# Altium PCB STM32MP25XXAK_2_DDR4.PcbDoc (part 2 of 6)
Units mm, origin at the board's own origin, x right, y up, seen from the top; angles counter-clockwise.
Board outline 120 x 79.6 mm, 4 copper layers (Top Layer, Signal Layer 1, Signal Layer 2, Bottom Layer), stack 1.614 mm thick; 243 components, 152 nets, 1304 pads, 784 vias.
Unrouted connection lines stored in the file: 6.
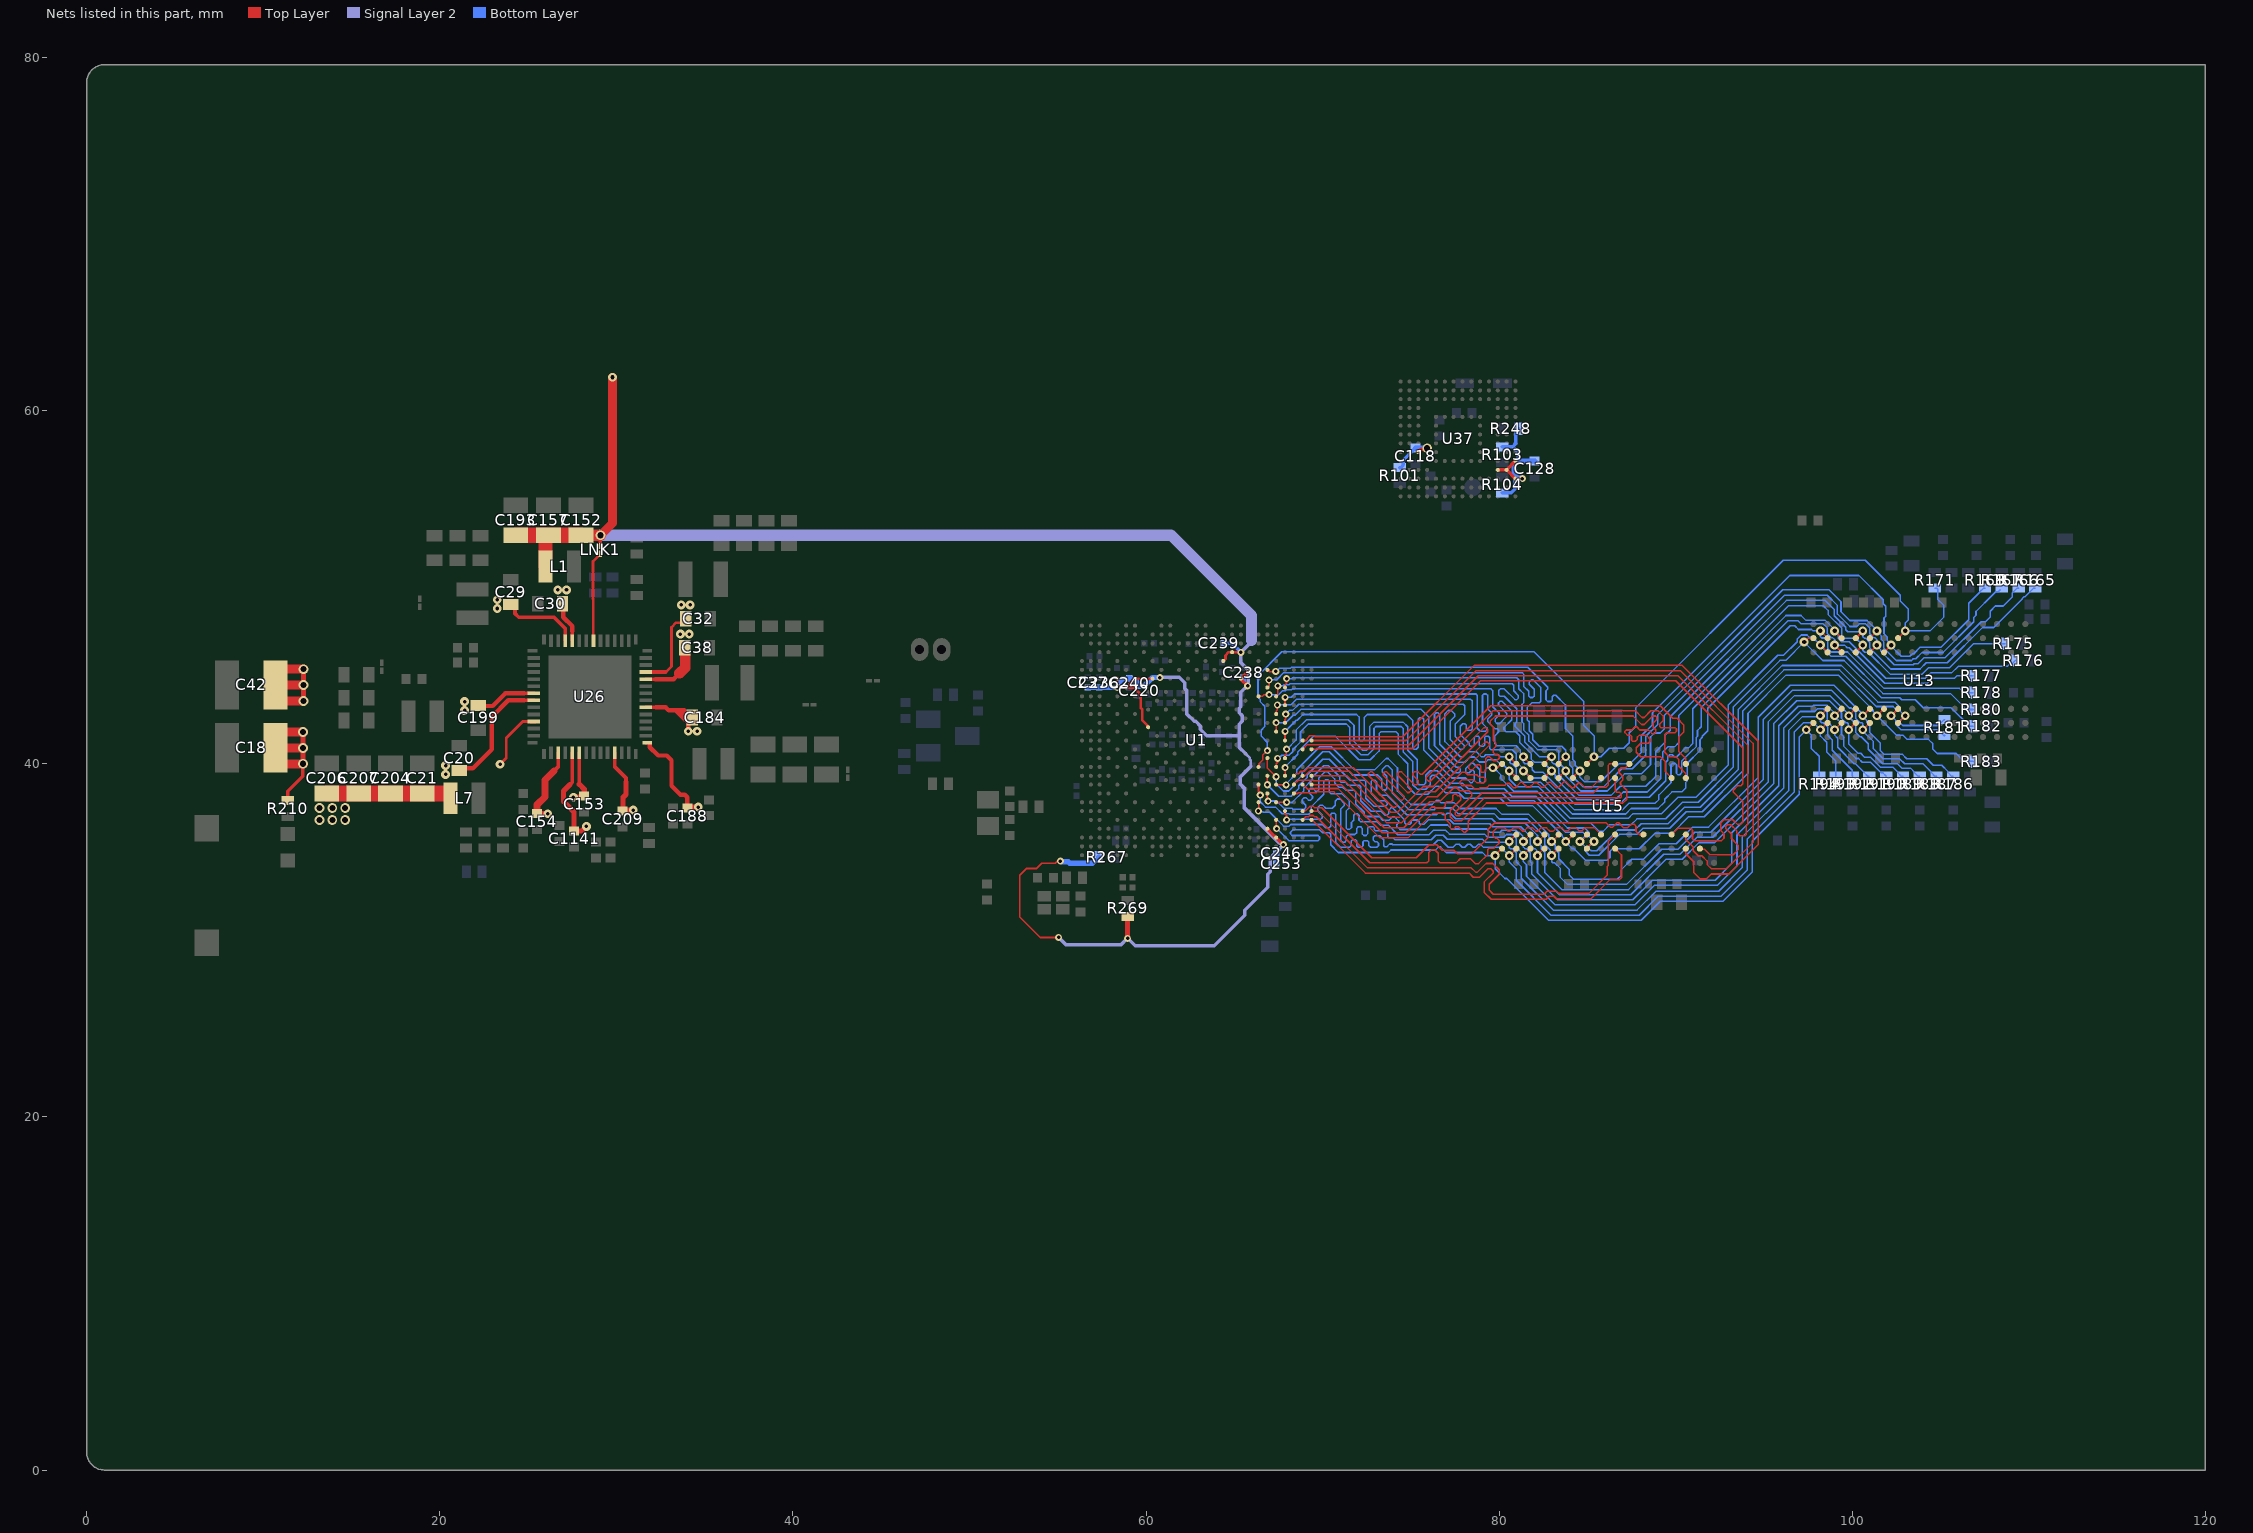
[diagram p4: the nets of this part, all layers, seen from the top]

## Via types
v1: diameter 0.55, hole 0.35, Top Layer to Bottom Layer, 256 vias
v2: diameter 0.4, hole 0.2, Top Layer to Bottom Layer, tented both sides, 235 vias
v3: diameter 0.5, hole 0.2, Top Layer to Bottom Layer, 146 vias
v4: diameter 0.5, hole 0.25, Top Layer to Bottom Layer, 143 vias
v5: diameter 0.5, hole 0.25, Top Layer to Bottom Layer, tented both sides, 4 vias

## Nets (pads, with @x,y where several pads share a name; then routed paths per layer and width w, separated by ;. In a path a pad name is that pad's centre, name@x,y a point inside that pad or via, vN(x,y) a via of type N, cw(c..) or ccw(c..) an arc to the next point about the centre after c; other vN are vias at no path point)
1V8: C118.2 C128.2 C152.2 C157.2 C193.2 C220.2 C236.2 C237.2 C238.2 C239.2 C240.2 C246.2 C253.2 L1.2 LNK1.2 R101.2 R103.2 R104.2 R248.2 R267.2 R269.1 U1.1E1 U1.AD22 U1.AE23 U1.D18 U1.E17 U1.F20 U1.G5 U1.G7 U1.G9 U1.G19 U1.H6 U37.C6 U37.M4 U37.N4 U37.P3 U37.P5 | length 134.2
  Top Layer w0.1: v2(55.049,30.165) 54.012,30.165 52.854,31.323 52.854,33.688 53.244,34.078 53.813,34.078 54.103,34.368 54.86,34.368 54.967,34.474 55.127,34.474 v2(55.146,34.494)
  Top Layer w0.15: U1.G5@58.375,44.825 v2(58.375,44.325) U1.H6@58.875,44.325 ; U1.1E1@60.125,42.075 60.125,42.097 60.085,42.137 60.085,42.17 59.791,42.464 59.791,43.079 59.702,43.168 59.702,43.926 59.304,44.325 U1.H6@58.875,44.325 ; U1.G9@60.375,44.825 U1.G7@59.375,44.825 U1.H6@58.875,44.325 ; U1.E17@64.375,45.825 64.375,45.828 64.5,45.953 64.5,46.139 64.683,46.322 U1.D18@64.872,46.322 ; U1.D18@64.875,46.325 65.372,46.325 v2(65.378,46.319) ; U37.P3@80.925,56.155 v2(81.325,56.155)
  Top Layer w0.18: v2(65.755,44.415) 65.4,44.77 65.4,44.786 65.375,44.811 U1.G19@65.375,44.825 U1.F20@65.875,45.325 ; U1.AD22@66.875,36.325 66.875,36.32 67.002,36.193 67.002,36.169 67.236,35.935 67.257,35.935 67.367,35.825 U1.AE23@67.375,35.825 v2(67.78,35.42)
  Top Layer w0.2: LNK1.2@29.1,52.348 v1(29.1,52.95) ; U37.C6@75.425,57.655 75.602,57.832 75.877,57.832 v1(75.925,57.88) ; U37.M4@79.925,56.655 U37.N4@80.425,56.655 ; U37.P3@80.925,56.155 U37.N4@80.425,56.655 ; U37.P5@80.925,57.155 U37.N4@80.425,56.655
  Top Layer w0.3: R269.1@58.956,31.358 58.956,30.117 v2(58.962,30.112)
  Top Layer w0.5: v1(29.1,52.95) 29.78,53.63 v4(29.78,61.9)
  Top Layer w0.64: C152.2@28,52.95 v1(29.1,52.95)
  Top Layer w0.8: L1.2@25.995,51.175 25.995,52.9 26.045,52.95 C157.2@26.15,52.95
  Top Layer w0.9: C193.2@24.3,52.95 C157.2@26.045,52.95 ; C157.2@26.15,52.95 C152.2@28,52.95
  Signal Layer 2 w0.15: 65.64,40.572 65.885,40.327 65.885,40.243 65.93,40.198 65.93,39.851
  Signal Layer 2 w0.2: v2(55.049,30.165) 55.449,29.766 58.598,29.766 v2@58.944,30.112 ; v2(58.962,30.112) 59.386,29.688 63.861,29.688 65.603,31.43 65.603,31.711 66.9,33.008 66.9,33.754 67.041,33.895 67.041,34.681 v2(67.78,35.42) 67.726,35.42 67.633,35.513 67.566,35.513 65.552,37.527 65.552,38.632 65.349,38.835 65.349,39.271 65.93,39.851 ; v2(60.79,44.885) 60.811,44.906 61.89,44.906 62.2,44.596 62.2,44.264 62.32,44.144 62.32,42.814 62.725,42.409 62.81,42.409 63.077,42.143 63.077,41.961 63.445,41.593 65.285,41.593 65.285,42.251 65.44,42.406 65.44,42.738 65.284,42.894 65.284,43.14 65.375,43.231 65.375,44.053 v2@65.734,44.411 ; 65.285,41.575 65.285,40.928 65.64,40.572 ; 65.794,44.612 65.794,45.317 65.378,45.733 v2(65.378,46.319) 65.933,46.874 65.933,46.95
  Signal Layer 2 w0.64: v1(29.1,52.95) 61.405,52.95 ; 61.411,52.956 65.971,48.396 65.971,46.988
  Bottom Layer w0.18: C238.2@65.5,44.883 65.585,44.798 65.585,44.63 65.755,44.46 v2(65.755,44.415) ; C246.2@67.391,34.986 67.436,34.986 67.46,35.01 67.46,35.054 67.57,35.164 67.57,35.175 67.78,35.385 v2(67.78,35.42)
  Bottom Layer w0.2: C239.2@64.4,46.837 64.86,46.837 v2(65.378,46.319) ; R101.2@74.375,56.775 74.425,56.775 74.58,56.93 74.58,57.2 75.08,57.7 75.08,57.725 75.235,57.88 C118.2@75.26,57.88 ; R103.2@80.171,57.961 80.769,57.961 ; R104.2@80.175,55.355 80.69,55.355 80.885,55.55 80.885,55.998 81.061,56.174 ; 81.075,57.136 81.075,57.655 80.769,57.961 ; R248.2@81.107,58.98 80.952,58.825 80.952,58.144 80.769,57.961
  Bottom Layer w0.25: C253.2@67.391,34.385 C246.2@67.391,34.925
  Bottom Layer w0.3: v2(55.146,34.494) 55.165,34.474 55.236,34.474 55.259,34.452 55.612,34.452 55.689,34.375 56.975,34.375 57.123,34.523 57.218,34.523 57.323,34.628 R267.2@57.323,34.723 ; C237.2@56.696,44.325 C236.2@57.35,44.325 v2(58.375,44.325) ; v2@58.386,44.325 v2(58.375,44.325) ; C240.2@58.984,44.85 C240.2@59.05,44.85 59.125,44.85 59.15,44.825 59.19,44.825 59.3,44.715 59.399,44.715 59.54,44.574 59.54,44.475 C220.2@59.609,44.406 59.634,44.431 59.911,44.431 60.372,44.892 60.783,44.892 v2(60.79,44.885) ; C240.2@59.025,44.825 58.689,44.825 58.394,44.53 58.394,44.344 v2(58.375,44.325) ; C118.2@75.26,57.88 v1(75.925,57.88) ; v2(81.325,56.155) 81.306,56.174 81.061,56.174 80.867,56.368 80.867,56.928 81.075,57.136 81.306,57.136 81.325,57.155 C128.2@82.015,57.155
1V8_FB: LNK1.1 U26.35 | length 5.1
  Top Layer w0.15: U26.35@28.7,46.97 28.7,49.311 28.675,49.336 28.675,51.473 LNK1.1@29.1,51.898
3V3: C21.2 C154.2 C204.2 C206.2 C207.2 L7.2 U26.3 U26.53 | length 15.3
  Top Layer w0.15: v3(23.41,39.977) 23.762,40.329 23.762,41.465 24.697,42.4 U26.53@25.33,42.4 ; U26.53@25.12,42.369 25.419,42.369 U26.53@25.45,42.4
  Top Layer w0.21: 26.473,39.598 26.7,39.825 U26.3@26.7,40.63
  Top Layer w0.3: C154.2@25.475,37.175 C154.2@25.5,37.175 v3@26.085,37.175
  Top Layer w0.4: C154.2@25.5,37.175 25.514,37.189 25.514,37.685 25.96,38.131 25.96,39.085 26.473,39.598
  Top Layer w0.9: C206.2@13.587,38.323 C21.2@19,38.323 20.362,38.323 L7.2@20.387,38.298
  other v1: 13.187,36.823 13.912,36.823 14.637,36.823 13.187,37.498 13.912,37.498 14.637,37.498
  other v3: 26.11,37.175
5V_STLK: C18.1 C20.2 C29.2 C30.2 C32.2 C38.2 C42.1 C153.2 C184.2 C188.2 C199.2 C209.2 R210.1 U26.6 U26.11 U26.15 U26.20 U26.24 U26.25 U26.38 U26.39 U26.49 U26.50 | length 58.9
  Top Layer w0.15: 32.8,45.2 33.125,45.525 33.125,47.731 33.388,47.994 33.819,47.994 C32.2@33.925,48.1
  Top Layer w0.2: R210.1@11.386,37.915 11.386,38.449 12.244,39.307 v1@12.244,39.994
  Top Layer w0.21: C29.2@24.025,49.05 24.262,48.813 24.262,48.513 24.475,48.3 26.464,48.3 27.1,47.664 U26.39@27.1,46.97 ; 24.775,43.6 U26.50@25.33,43.6 ; 24.775,44 U26.49@25.33,44 ; U26.38@27.5,46.97 27.5,47.525 ; 27.9,38.85 U26.6@27.9,40.63 ; U26.11@29.9,40.63 29.9,39.843 30.54,39.203 30.54,38.975 ; U26.15@31.67,41.2 U26.15@31.745,41.2 U26.15@31.785,41.2 ; U26.20@31.67,43.2 32.225,43.2 ; U26.24@31.67,44.8 32.207,44.8 ; U26.25@31.67,45.2 32.8,45.2
  Top Layer w0.25: C20.2@21.1,39.75 21.875,39.75 22.95,40.825 22.95,42.669 23.881,43.6 24.775,43.6 ; C199.2@22.175,43.275 22.991,43.275 23.716,44 24.775,44 ; C30.2@26.925,49.075 26.994,49.006 26.994,48.308 27.5,47.802 27.5,47.525 ; 31.895,41.095 31.895,40.947 32.371,40.472 32.853,40.472 33.125,40.2 33.125,38.759 33.634,38.25 33.879,38.25 34.025,38.104 C188.2@34.025,37.55 ; 32.207,44.8 33.25,44.8 33.575,45.125 ; 32.225,43.2 32.788,43.2 32.963,43.025 33.358,43.025 ; v3(34.075,41.85) 34.075,42.308 33.358,43.025 ; 33.358,43.025 33.579,43.025 ; 33.579,43.025 33.847,43.025 33.972,42.9 34.05,42.9 34.247,42.703 34.247,42.625 34.246,42.627 33.977,42.627 33.579,43.025
  Top Layer w0.3: v1@12.25,40 12.25,40.906 v1@12.25,41.8 ; v1@12.275,43.563 v1@12.275,45.363 ; v3(27.565,38.11) 28.175,38.11 28.174,38.111 28.174,38.576 27.9,38.85 ; C209.2@30.35,37.38 C209.2@30.375,37.38 ; 30.54,38.975 30.54,38.269 30.375,38.104 C209.2@30.375,37.38 ; v3(30.96,37.38) C209.2@30.375,37.38 ; C188.2@34.025,37.55 v3(34.635,37.55)
  Top Layer w0.5: C18.1@10.686,39.994 12.244,39.994 v1@12.269,39.994 ; C18.1@10.686,40.906 12.25,40.906 v1@12.269,40.906 ; C18.1@10.686,41.806 v1@12.269,41.806 ; C42.1@10.686,43.557 v1@12.269,43.557 ; C42.1@10.686,44.468 v1@12.269,44.468 ; C42.1@10.686,45.368 v1@12.269,45.368
  Top Layer w0.6: 33.575,45.125 33.9,45.45 C38.2@33.9,46.175
  other v1: 12.251,40.002 12.251,40.902 12.251,41.802 12.276,43.565 12.276,44.465 12.276,45.365
  other v3: 20.325,39.4 20.325,39.9 34.575,41.85 21.4,43.025 21.4,43.525 33.625,47.35 34.125,47.35 23.25,48.8 33.675,49 34.175,49 23.25,49.3 26.675,49.85 27.175,49.85
5V_VCONN: C1141.1 U26.5 | length 5.7
  Top Layer w0.21: 27.378,38.827 27.5,38.95 U26.5@27.5,40.63
  Top Layer w0.3: 27.378,38.827 27.01,38.46 27.01,37.865 27.6,37.275 C1141.1@27.6,36.2 28.04,36.2 v3(28.3,36.46)
DDR_A0: R177.1 U1.L23 U13.P3 U15.P3 | length 58.8
  Top Layer w0.09: U1.L23@67.375,42.825 67.375,42.997 67.445,43.068 v2@67.445,43.333 ; v4@81.381,39.6 81.421,39.6 81.774,39.247 U15.P3@81.774,39.197 ; v4(99.003,46.729) 99.003,46.722 U13.P3@99.405,46.32
  Bottom Layer w0.09: v2@67.45,43.338 68.202,43.338 68.529,43.665 78.379,43.665 78.476,43.568 78.476,41.97 78.405,41.899 78.221,41.899 78.151,41.969 78.151,42.179 78.062,42.268 77.943,42.268 77.806,42.13 77.806,41.669 78.306,41.168 78.306,41.068 78.38,40.995 78.518,40.995 78.597,41.074 78.597,41.489 78.672,41.564 78.814,41.564 78.887,41.491 78.887,41.063 78.958,40.991 79.113,40.991 79.179,41.058 79.179,41.49 79.248,41.558 79.403,41.558 79.475,41.486 79.475,40.868 79.54,40.804 80.749,40.804 80.978,40.575 80.978,40.107 81.378,39.707 v4(81.378,39.604) 81.781,39.201 82.46,39.201 84.249,37.412 87.01,37.412 87.378,37.779 88.853,37.779 89.053,37.979 89.053,38.238 89.74,38.925 89.74,39.945 89.816,40.021 89.972,40.021 90.051,39.942 90.051,39.458 90.13,39.38 90.228,39.38 90.354,39.506 90.354,40.162 90.861,40.669 91.177,40.985 91.177,41.497 91.237,41.558 91.237,41.888 91.449,42.1 91.449,43.195 96.366,48.112 96.93,48.112 97.117,47.925 98.367,47.925 98.598,47.694 98.598,47.375 98.839,47.134 98.911,47.134 99.003,47.042 v4(99.003,46.729) v4@98.988,46.744 ; v4@99.028,46.729 99.568,46.729 99.723,46.574 99.84,46.574 101.852,44.562 104.265,44.562 104.562,44.859 105.804,44.859 105.924,44.979 R177.1@106.853,44.979
  other v2: 67.44,43.333
DDR_A1: R190.1 U1.Y22 U13.P7 U15.P7 | length 54.8
  Top Layer w0.09: U1.Y22@66.875,38.325 66.875,37.932 v2(66.912,37.895) ; v4@81.381,35.6 U15.P7@81.781,36 ; v4(99.003,42.729) 99.394,43.12 U13.P7@99.405,43.12
  Bottom Layer w0.09: v2@66.94,37.867 v2(66.912,37.895) 67.398,37.895 67.813,37.48 68.27,37.48 68.317,37.434 68.958,37.434 69.055,37.531 69.055,37.648 68.854,37.849 68.854,37.98 68.959,38.085 69.067,38.085 69.204,37.948 69.329,37.948 69.433,38.052 69.433,38.156 69.435,38.158 69.435,38.162 69.235,38.362 69.235,38.511 69.339,38.615 69.446,38.615 69.602,38.46 69.717,38.46 69.782,38.524 69.782,39.193 70.139,39.55 70.277,39.55 70.681,39.145 70.681,38.924 70.926,38.68 71.147,38.68 71.33,38.496 71.792,38.496 71.872,38.417 71.872,37.745 72.362,37.255 72.362,37.093 72.436,37.019 73.194,37.019 73.413,36.801 73.77,36.801 73.967,36.998 74.07,36.998 74.306,36.762 74.306,36.655 74.208,36.556 74.208,36.457 74.384,36.281 75.865,36.281 76.12,36.537 77.082,36.537 77.307,36.312 79.298,36.312 79.473,36.136 80.053,36.136 80.153,36.236 80.943,36.236 81.055,36.124 81.131,36.124 81.332,35.923 81.332,35.65 v4(81.378,35.604) ; v4@81.378,35.595 81.378,35.283 81.462,35.199 81.541,35.199 81.773,34.968 81.773,34.473 81.843,34.403 81.843,33.76 83.304,32.299 87.572,32.299 88.686,33.413 92.246,33.413 93.184,34.351 93.184,36.099 95.838,38.752 95.838,42.153 96.945,43.261 97.755,43.261 97.809,43.314 98.566,43.314 99.003,42.877 v4(99.003,42.729) ; v4@99.07,42.689 99.07,42.609 99.398,42.282 99.398,41.659 99.513,41.544 99.513,41.009 100.216,40.305 100.362,40.305 100.578,40.089 101.045,40.089 101.622,39.512 101.718,39.512 R190.1@101.928,39.302
DDR_A2: R180.1 U1.N23 U13.R3 U15.R3 | length 61.7
  Top Layer w0.09: v2(67.366,42.334) 67.375,42.325 U1.N23@67.375,41.825 ; v4@80.581,39.6 80.621,39.6 80.974,39.247 U15.R3@80.974,39.197 ; v4(98.203,46.729) 98.605,46.327 U13.R3@98.605,46.32
  Bottom Layer w0.09: v2(67.366,42.334) 67.375,42.325 67.911,42.325 68.343,42.758 68.442,42.758 68.769,43.085 75.595,43.085 76.022,42.657 76.022,40.899 77.432,39.489 77.72,39.489 77.812,39.581 77.812,39.713 77.723,39.802 77.568,39.802 76.339,41.03 76.339,42.802 76.435,42.897 76.537,42.897 76.642,42.792 76.642,41.111 77.664,40.09 78.058,40.09 78.359,40.39 78.593,40.39 78.879,40.105 79.25,40.105 79.369,40.224 79.831,40.224 80.049,40.005 80.173,40.005 v4@80.574,39.604 ; v4(80.578,39.604) 80.578,39.121 81,38.699 82.238,38.699 84.027,36.91 87.31,36.91 87.563,37.162 87.58,37.178 89.201,37.178 90.139,38.116 91.156,38.116 92.978,39.937 92.978,43.338 95.789,46.149 96.113,46.149 96.883,46.919 96.883,47.068 97.114,47.299 97.441,47.299 97.582,47.158 97.773,47.158 v4(98.203,46.729) 98.203,46.685 98.796,46.092 99.632,46.092 101.742,43.982 105.573,43.982 106.478,43.077 R180.1@106.853,43.077
DDR_A3: R188.1 U1.V22 U13.N7 U15.N7 | length 57.5
  Top Layer w0.09: v2(66.873,38.817) U1.V22@66.873,39.323 ; v4@82.181,35.6 82.204,35.6 82.574,35.97 U15.N7@82.574,35.997 ; v4(99.803,42.729) 100.194,43.12 U13.N7@100.205,43.12
  Bottom Layer w0.09: v2(66.873,38.817) 67.52,38.17 68.223,38.17 68.655,38.602 68.655,38.753 69.126,39.224 69.126,39.383 70.012,40.268 70.379,40.268 71.571,39.076 72.379,39.076 72.452,39.003 72.452,38.059 72.909,37.602 73.566,37.602 73.658,37.694 73.658,37.807 73.638,37.825 73.55,37.913 73.162,37.913 72.751,38.325 72.751,38.996 72.831,39.076 72.967,39.076 73.055,38.988 73.055,38.478 73.305,38.228 73.665,38.228 73.665,38.223 74.772,37.117 76.446,37.117 76.538,37.209 76.725,37.209 76.817,37.117 76.966,37.117 77.058,37.209 77.23,37.209 77.547,36.892 79.586,36.892 79.835,36.643 81.475,36.643 82.178,35.94 v4(82.178,35.604) 82.178,35.554 82.378,35.354 82.378,35.198 82.582,34.994 82.582,33.841 83.544,32.879 87.331,32.879 89.331,34.879 90.25,34.879 91.209,35.838 92.103,35.838 95.258,38.993 95.258,42.393 96.733,43.869 98.724,43.869 99.803,42.79 v4(99.803,42.729) 99.803,42.672 100.198,42.277 100.198,41.775 100.439,41.534 100.521,41.534 100.913,41.143 100.913,40.828 101.737,40.004 102.564,40.004 102.808,39.76 103.306,39.76 103.523,39.543 103.523,39.512 103.733,39.302 R188.1@103.828,39.302
DDR_A4: R175.1 U1.J21 U13.N3 U15.N3 | length 60.4
  Top Layer w0.09: U1.J21@66.381,43.819 66.581,43.819 66.683,43.921 v2(66.971,43.921) ; U15.N3@82.574,39.197 82.574,39.245 v4@82.929,39.6 ; U13.N3@100.205,46.32 100.603,46.718 v4(100.603,46.729)
  Bottom Layer w0.09: v2(66.971,43.921) 67.509,43.921 67.719,44.131 67.89,44.131 67.948,44.19 68.223,44.19 68.278,44.245 79.54,44.245 79.647,44.139 79.647,43.23 79.995,42.881 79.995,42.741 79.773,42.519 79.773,42.399 79.902,42.271 80.019,42.271 80.425,42.676 80.425,42.867 79.965,43.328 79.965,43.452 80.05,43.536 80.177,43.536 80.717,42.997 80.717,42.501 80.277,42.061 80.277,41.942 80.393,41.825 80.941,41.825 81.173,41.593 81.173,41.222 81.176,41.219 81.176,41.21 81.832,40.553 81.832,40.252 82.001,40.084 82.502,40.084 v4@82.978,39.608 ; v4(82.978,39.604) 82.978,39.566 83.194,39.35 83.194,39.192 84.425,37.961 86.585,37.961 87.028,38.404 88.393,38.404 89.158,39.169 89.158,40.213 89.27,40.325 89.27,40.672 89.558,40.959 89.941,40.959 90.173,41.19 90.173,42.739 96.396,48.962 98.359,48.962 98.636,48.686 98.636,48.458 99.405,47.689 99.405,47.22 99.503,47.122 100.21,47.122 v4(100.603,46.729) 100.603,46.433 100.709,46.327 100.905,46.327 102.148,45.084 103.967,45.084 104.322,45.439 105.512,45.439 106.875,46.802 R175.1@108.678,46.802
DDR_A5: R191.1 U1.W21 U13.P8 U15.P8 | length 55.4
  Top Layer w0.09: U1.W21@66.375,38.825 U1.W21@66.375,38.825 66.374,38.416 66.469,38.321 v2@66.469,38.237 ; v4@81.381,34.8 81.381,34.83 U15.P8@81.75,35.199 ; v4@99.005,41.926 U13.P8@99.402,42.323
  Bottom Layer w0.09: v2@66.469,38.153 v2@66.469,38.237 ; v2(66.47,38.23) 66.47,37.849 66.769,37.55 67.333,37.55 67.713,37.17 68.104,37.17 68.13,37.144 69.213,37.144 69.371,37.302 69.371,37.58 70.072,38.281 70.072,39.012 70.165,39.106 70.311,39.106 70.391,39.025 70.391,38.395 70.489,38.298 71.119,38.298 71.521,37.896 71.521,37.52 71.332,37.332 71.332,36.366 71.413,36.286 71.533,36.286 71.641,36.394 71.641,36.68 71.765,36.804 71.765,37.095 71.839,37.169 71.979,37.169 72.063,37.085 72.063,36.818 72.152,36.729 73.074,36.729 73.293,36.511 73.744,36.511 74.264,35.991 76.035,35.991 76.29,36.247 76.962,36.247 77.187,36.022 79.178,36.022 79.353,35.846 80.261,35.846 80.414,35.999 80.741,35.999 80.973,35.768 80.973,35.276 81.378,34.871 v4(81.378,34.804) v4@81.416,34.765 ; v4@81.378,34.765 81.378,34.458 81.526,34.309 81.553,34.283 81.553,33.64 83.184,32.009 87.692,32.009 88.806,33.123 92.366,33.123 93.474,34.231 93.474,35.979 96.128,38.632 96.128,42.033 97.063,42.968 97.883,42.968 98.039,43.124 98.366,43.124 98.598,42.893 98.598,42.383 99.003,41.978 99.003,41.629 99.178,41.454 99.178,40.934 100.096,40.015 100.175,40.015 100.673,39.518 100.673,39.512 100.883,39.302 R191.1@100.978,39.302
  other v4: 99.003,41.929
DDR_A6: R176.1 U1.K24 U13.P2 U15.P2 | length 60.6
  Top Layer w0.09: U1.K24@67.875,43.325 v2(67.875,43.77) ; v4@81.376,40.395 81.749,40.022 U15.P2@81.774,40.022 ; v4(99.003,47.529) 99.003,47.522 U13.P2@99.405,47.12
  Bottom Layer w0.09: v2(67.875,43.77) 68.224,43.77 68.409,43.955 78.691,43.955 78.766,43.88 78.766,42.022 78.94,41.848 79.225,41.848 79.316,41.94 79.316,42.034 79.059,42.291 79.059,43.883 79.131,43.955 79.284,43.955 79.357,43.883 79.357,43.11 79.584,42.882 79.584,42.766 79.357,42.538 79.357,42.406 79.782,41.981 79.916,41.981 79.986,41.911 79.986,41.811 79.765,41.59 79.765,41.132 79.866,41.031 80.967,41.031 81.188,40.809 81.188,40.662 81.378,40.472 v4(81.378,40.404) ; v4(81.378,40.404) 81.378,40.09 81.46,40.008 81.659,40.008 81.883,39.785 81.883,39.665 82.022,39.526 82.492,39.526 84.316,37.702 86.81,37.702 87.221,38.112 88.506,38.112 88.508,38.114 88.513,38.114 89.448,39.048 89.448,40.093 89.56,40.205 89.56,40.406 89.674,40.52 89.81,40.52 89.923,40.407 90.057,40.407 90.554,40.904 90.727,40.904 90.973,41.149 90.973,41.616 90.97,41.618 90.97,43.126 96.246,48.402 97.106,48.402 97.383,48.125 98.486,48.125 99.003,47.608 v4(99.003,47.529) ; v4@99.003,47.527 99.205,47.325 99.205,47.12 99.405,46.92 99.836,46.92 101.905,44.852 104.145,44.852 104.442,45.149 105.632,45.149 106.003,45.52 108.786,45.52 108.89,45.624 109.018,45.624 109.228,45.834 R176.1@109.228,45.852
DDR_A7: R193.1 U1.AA21 U13.R8 U15.R8 | length 52.8
  Top Layer w0.09: v2@66.375,37.33 U1.AA21@66.375,37.825 ; v4@80.581,34.8 U15.R8@80.981,35.2 ; v4(98.203,41.929) 98.594,42.32 U13.R8@98.605,42.32
  Bottom Layer w0.09: v2(66.365,37.33) 66.405,37.29 66.619,37.29 66.649,37.26 67.003,37.26 67.79,36.474 68.113,36.474 68.203,36.564 69.989,36.564 70.173,36.38 70.367,36.38 70.459,36.472 70.459,37.133 70.527,37.201 70.683,37.201 70.752,37.132 70.752,35.535 71.017,35.27 71.523,35.27 71.625,35.372 71.625,35.629 71.702,35.706 71.864,35.706 71.935,35.635 71.935,35.363 72.029,35.27 72.2,35.27 72.292,35.362 72.292,35.579 72.366,35.653 72.538,35.653 72.608,35.583 72.608,35.397 72.735,35.27 73.072,35.27 73.169,35.367 73.169,35.509 73.083,35.595 72.973,35.595 72.878,35.69 72.878,35.846 72.959,35.927 73.235,35.927 73.463,35.699 73.463,35.363 73.53,35.295 73.636,35.295 73.798,35.458 73.938,35.458 73.984,35.411 76.275,35.411 76.531,35.667 76.721,35.667 77.117,35.271 77.389,35.271 77.56,35.442 77.742,35.442 77.91,35.273 78.062,35.273 78.23,35.442 78.37,35.442 78.538,35.273 78.665,35.273 78.834,35.442 78.937,35.442 79.113,35.266 80.109,35.266 80.571,34.804 v4(80.578,34.804) ; v4@80.596,34.785 v4(80.578,34.804) ; R193.1@99.078,39.302 99.078,40.15 98.56,40.668 98.56,41.223 98.203,41.58 v4(98.203,41.929) 97.807,42.324 97.239,42.324 96.708,41.793 96.708,38.392 94.054,35.739 94.054,33.991 92.564,32.5 89.003,32.5 87.932,31.429 82.943,31.429 80.973,33.4 80.973,34.043 80.946,34.069 80.578,34.438 v4(80.578,34.804)
DDR_A8: R178.1 U1.M24 U13.R2 U15.R2 | length 60.5
  Top Layer w0.09: U1.M24@67.875,42.325 67.875,42.519 67.911,42.555 67.911,42.816 v2(67.916,42.821) ; v4@80.574,40.397 U15.R2@80.974,39.997 ; v4(98.203,47.529) 98.605,47.127 U13.R2@98.605,47.12
  Bottom Layer w0.09: v2(67.916,42.821) 68.143,43.048 68.322,43.048 68.649,43.375 77.971,43.375 78.052,43.294 78.052,42.796 77.516,42.26 77.516,41.548 78.016,41.048 78.016,40.923 77.931,40.839 77.772,40.839 77.223,41.388 77.223,42.417 77.498,42.692 77.498,42.808 77.284,43.021 77.111,43.021 76.932,42.842 76.932,41.268 77.8,40.4 77.959,40.4 78.238,40.68 78.717,40.68 79.002,40.395 79.13,40.395 79.249,40.514 79.951,40.514 80.068,40.396 80.57,40.396 v4(80.578,40.404) ; v4@80.617,40.355 80.617,40.072 80.69,39.999 80.741,39.999 80.978,39.763 80.978,39.304 81.331,38.951 82.351,38.951 84.14,37.162 87.171,37.162 87.478,37.47 89.005,37.47 89.377,37.842 89.377,37.99 89.796,38.409 90.341,38.409 90.583,38.65 90.583,38.968 90.653,39.038 90.653,40.029 91.383,40.759 91.383,41.368 91.515,41.5 91.515,41.567 91.817,41.869 91.817,43.153 96.487,47.822 96.747,47.822 96.96,47.609 97.701,47.609 97.781,47.529 v4@98.178,47.529 ; v4@98.202,47.505 v4@98.178,47.529 ; R178.1@106.853,44.029 106.328,44.029 106.085,44.272 101.803,44.272 99.741,46.334 98.823,46.334 98.608,46.549 98.608,46.955 98.434,47.129 98.269,47.129 98.203,47.196 v4(98.203,47.529) v4@98.178,47.529
DDR_A9: R192.1 U1.AB24 U13.R7 U15.R7 | length 52.4
  Top Layer w0.09: U1.AB24@67.875,37.325 67.875,37.175 67.961,37.09 v2@67.961,36.85 ; v4@80.581,35.6 80.974,35.993 U15.R7@80.974,35.997 ; v4(98.203,42.729) U13.R7@98.599,43.126
  Bottom Layer w0.09: v2@67.965,36.854 69.882,36.854 69.978,36.95 69.978,37.091 69.731,37.338 69.731,37.53 69.848,37.647 70.023,37.647 70.178,37.491 70.546,37.491 70.717,37.663 70.717,37.889 70.836,38.008 70.999,38.008 71.231,37.776 71.231,37.64 71.042,37.452 71.042,35.655 71.138,35.56 71.253,35.56 71.335,35.641 71.335,35.876 71.455,35.996 71.828,35.996 71.931,36.1 71.931,36.338 72.028,36.435 72.162,36.435 72.255,36.342 72.255,36.031 72.343,35.943 72.462,35.943 72.55,36.031 72.55,36.365 72.623,36.438 72.859,36.438 72.937,36.36 72.937,36.27 72.986,36.221 73.624,36.221 73.689,36.156 73.689,35.883 73.752,35.82 73.986,35.82 74.104,35.701 76.155,35.701 76.41,35.957 76.842,35.957 77.067,35.732 79.057,35.732 79.233,35.556 80.381,35.556 80.503,35.678 v4(80.578,35.604) 80.578,35.254 80.633,35.199 80.741,35.199 80.977,34.963 80.977,34.448 81.236,34.189 81.263,34.163 81.263,33.52 83.064,31.719 87.812,31.719 88.883,32.79 92.443,32.79 93.764,34.111 93.764,35.859 96.418,38.512 96.418,41.913 97.183,42.678 98.152,42.678 v4(98.203,42.729) ; v4@98.207,42.724 98.207,42.397 98.275,42.329 98.364,42.329 98.605,42.087 98.605,41.616 98.866,41.356 98.866,40.775 100.001,39.639 100.001,39.329 R192.1@100.028,39.302
  other v2: 67.96,36.825
DDR_A10: R166.1 U1.H24 U13.M3 U15.M3 | length 58.7
  Top Layer w0.09: U1.H24@67.875,44.325 67.877,44.327 67.877,44.497 67.96,44.58 v2(67.96,44.825) ; U15.M3@83.374,39.197 83.374,39.245 v4@83.729,39.6 ; U13.M3@101.005,46.32 101.403,46.718 v4(101.403,46.729)
  Bottom Layer w0.09: v2(67.96,44.825) 68.242,44.825 68.297,44.88 81.002,44.88 81.117,44.764 81.117,44.254 81.386,43.985 81.386,43.452 81.297,43.363 81.297,42.378 81.386,42.289 81.386,41.921 81.691,41.617 81.691,41.294 82.178,40.807 83.285,40.807 83.373,40.719 83.373,40.07 83.778,39.665 83.778,39.315 84.632,38.461 86.13,38.461 87.098,39.429 88.053,39.429 88.578,39.954 88.578,41.524 88.802,41.749 89.125,41.749 89.349,41.972 89.349,42.735 96.171,49.558 98.584,49.558 99.166,48.976 99.166,48.487 99.875,47.779 100.264,47.779 100.411,47.926 100.767,47.926 100.998,47.694 100.998,47.375 101.239,47.134 101.306,47.134 101.397,47.043 101.397,46.735 v4(101.403,46.729) 101.403,46.676 101.608,46.471 101.608,46.387 102.381,45.614 103.464,45.614 103.514,45.664 103.727,45.664 104.082,46.019 105.271,46.019 107.305,48.052 107.554,48.052 107.816,48.314 107.816,48.651 108.107,48.942 108.556,48.942 109.078,49.464 109.078,49.697 109.333,49.952 R166.1@109.428,49.952 R166.1@109.428,49.954
  other v4: 83.778,39.604
DDR_A11: R182.1 U1.P24 U13.T2 U15.T2 | length 63.3
  Top Layer w0.09: U1.P24@67.875,41.325 67.875,41.838 v2(67.879,41.842) ; v4@79.656,39.775 79.904,39.775 80.128,39.999 U15.T2@80.175,39.999 ; v4(97.278,46.904) 97.494,47.12 U13.T2@97.805,47.12
  Bottom Layer w0.09: v2@67.88,41.842 68.506,42.468 68.562,42.468 68.889,42.795 71.929,42.795 72.07,42.654 72.07,41.391 72.143,41.318 72.278,41.318 72.373,41.413 72.373,42.636 72.532,42.795 74.776,42.795 75.112,42.458 75.112,40.897 75.178,40.831 75.307,40.831 75.423,40.947 75.423,42.532 75.499,42.607 75.646,42.607 75.732,42.521 75.732,40.779 77.312,39.199 78.113,39.199 ; 78.113,39.2 78.375,38.938 78.468,38.938 78.594,39.064 78.594,39.562 78.518,39.638 78.45,39.638 78.309,39.497 78.168,39.497 78.102,39.563 78.102,39.722 78.417,40.037 78.536,40.037 78.906,39.668 78.906,39.011 78.984,38.932 79.113,38.932 79.225,39.044 79.225,39.677 79.327,39.779 v4(79.653,39.779) 79.693,39.779 80.103,39.369 80.103,39.174 80.825,38.451 82.144,38.451 83.939,36.655 85.186,36.655 85.671,36.171 85.885,36.171 86.259,36.545 87.478,36.545 87.808,36.874 ; 87.809,36.874 87.825,36.89 89.446,36.89 90.384,37.828 91.278,37.828 93.268,39.817 93.268,43.217 95.909,45.859 96.233,45.859 v4(97.278,46.904) ; v4(97.278,46.904) 98.327,45.854 99.542,45.854 101.658,43.738 102.695,43.738 102.804,43.629 103.578,43.629 104.023,43.184 105.598,43.184 106.653,42.129 R182.1@106.853,42.129
DDR_A12: R186.1 U1.W23 U13.M7 U15.M7 | length 55.3
  Top Layer w0.09: U1.W23@67.379,38.821 67.918,38.821 v2(67.935,38.805) ; v4@83.004,35.6 83.374,35.97 U15.M7@83.374,35.997 ; v4(100.603,42.729) 100.994,43.12 U13.M7@101.005,43.12 ; v4@100.612,42.703 v4@100.635,42.703
  Bottom Layer w0.09: v2(67.935,38.805) 67.935,38.853 68.546,39.464 68.546,39.67 69.849,40.972 70.495,40.972 71.811,39.656 72.949,39.656 73.598,40.305 73.708,40.305 74.245,39.767 74.245,38.463 75.012,37.697 76.205,37.697 76.45,37.942 76.576,37.942 76.728,37.789 77.47,37.789 77.787,37.472 79.826,37.472 80.162,37.136 81.688,37.136 82.821,36.004 82.821,35.862 82.978,35.705 v4(82.978,35.604) 83.188,35.393 83.188,35.152 83.373,34.968 83.373,34.619 83.983,34.009 83.983,33.69 84.214,33.459 86.691,33.459 86.928,33.695 86.928,34.013 87.519,34.604 88.181,34.604 89.056,35.479 90.03,35.479 90.968,36.418 91.862,36.418 94.678,39.233 94.678,42.633 96.493,44.449 98.965,44.449 100.603,42.812 100.603,42.688 100.817,42.474 100.817,42.346 100.999,42.164 100.999,41.774 101.583,41.19 101.583,40.765 101.814,40.534 102.854,40.534 103.094,40.294 104.222,40.294 104.599,39.918 105.068,39.918 105.423,39.563 105.423,39.512 105.633,39.302 R186.1@105.728,39.302
DDR_A13: R194.1 U1.AC23 U13.T8 U15.T8 | length 49.2
  Top Layer w0.09: U1.AC23@67.379,36.821 67.379,36.358 v2(67.402,36.335) ; v4@79.781,34.8 79.781,34.83 U15.T8@80.15,35.199 ; v4(97.403,41.929) 97.414,41.929 U13.T8@97.805,42.32 ; v4@97.412,41.933 v4@97.484,42.005
  Bottom Layer w0.09: v2(67.402,36.335) 68.084,35.653 69.753,35.653 69.827,35.728 69.827,35.858 69.742,35.944 68.272,35.944 68.183,36.032 68.183,36.132 68.325,36.274 69.826,36.274 70.009,36.091 70.378,36.091 70.462,36.007 70.462,35.415 70.897,34.98 73.731,34.98 73.872,35.121 76.395,35.121 76.565,35.291 76.687,35.291 76.997,34.981 79.056,34.981 79.233,34.804 v4(79.778,34.804) ; v4@79.781,34.8 79.781,34.058 80.331,33.507 80.432,33.507 82.8,31.139 88.052,31.139 89.123,32.21 92.684,32.21 94.344,33.871 94.344,35.618 96.998,38.272 96.998,41.516 v4@97.403,41.921 ; v4@97.403,41.785 v4@97.43,41.785 ; v4(97.403,41.929) v4@97.403,41.921 ; R194.1@98.132,39.302 98.132,40.424 97.688,40.869 97.688,41.636 v4@97.403,41.921
DDR_ACTN: R168.1 U1.F22 U13.L3 U15.L3 | length 58.7
  Top Layer w0.09: U1.F22@66.883,45.325 66.888,45.325 66.998,45.215 67.317,45.215 v2@67.34,45.239 ; U15.L3@84.174,39.197 84.174,39.245 84.529,39.6 v4@84.581,39.6 ; U13.L3@101.805,46.32 102.203,46.718 v4(102.203,46.729)
  Bottom Layer w0.09: v2@67.35,45.239 67.386,45.239 67.558,45.41 68.19,45.41 68.258,45.478 81.618,45.478 82.764,44.332 82.764,44.242 82.656,44.135 82.656,43.625 82.748,43.534 82.963,43.534 83.016,43.586 83.016,43.807 83.1,43.891 83.21,43.891 83.763,43.338 83.763,41.997 84.178,41.582 84.178,40.242 84.306,40.114 84.306,39.927 84.368,39.865 84.368,39.862 84.578,39.652 v4(84.578,39.604) 84.578,39.242 84.841,38.979 85.765,38.979 86.795,40.009 87.422,40.009 88.056,40.643 88.056,41.588 88.688,42.22 88.688,42.895 96.463,50.67 100.383,50.67 101.762,49.291 101.762,49.066 101.898,48.931 101.898,48.358 101.803,48.263 101.803,47.368 101.984,47.187 101.984,46.988 v4@102.203,46.769 ; v4@102.203,46.672 102.78,46.094 103.266,46.094 103.416,46.244 103.486,46.244 103.841,46.599 105.031,46.599 106.598,48.165 106.598,49.099 107.223,49.724 107.223,49.742 107.433,49.952 R168.1@107.528,49.952
  other v2: 67.35,45.24
DDR_BA0: R165.1 U1.J23 U13.N2 U15.N2 | length 62.1
  Top Layer w0.09: U1.J23@67.375,43.825 67.471,43.921 v2(67.471,44.421) ; U15.N2@82.574,39.997 82.574,40.045 v4@82.904,40.375 ; U13.N2@100.205,47.12 100.603,47.518 v4(100.603,47.529)
  Bottom Layer w0.09: v2(67.471,44.421) 67.77,44.421 67.828,44.48 68.103,44.48 68.158,44.535 80.752,44.535 80.827,44.46 80.827,44.134 81.096,43.865 81.096,43.727 81.008,43.639 80.897,43.639 80.291,44.245 80.059,44.245 79.985,44.171 79.985,43.903 80.061,43.826 80.298,43.826 81.007,43.117 81.007,42.381 80.899,42.274 80.899,42.136 81.443,41.593 81.443,41.245 82.284,40.404 v4(82.978,40.404) v4@82.952,40.378 ; v4@82.978,40.379 82.978,40.101 83.08,39.999 83.143,39.999 83.376,39.766 83.376,39.447 83.528,39.295 83.528,39.212 84.528,38.211 86.34,38.211 86.86,38.731 88.31,38.731 88.868,39.289 88.868,40.685 89.373,41.19 89.373,41.579 89.698,41.904 89.698,42.674 96.282,49.259 98.473,49.259 98.976,48.756 98.976,48.409 98.99,48.394 98.99,48.389 99.639,47.74 99.639,47.602 99.753,47.489 100.562,47.489 v4(100.603,47.529) 100.603,47.204 100.683,47.124 100.766,47.124 100.998,46.893 100.998,46.559 102.183,45.374 103.847,45.374 104.202,45.729 105.392,45.729 107.388,47.725 108.019,47.725 109.628,49.334 109.628,49.369 109.713,49.454 109.776,49.454 110.276,49.954 R165.1@110.378,49.954
DDR_BA1: R189.1 U1.AA23 U13.N8 U15.N8 | length 52.5
  Top Layer w0.09: U1.AA23@67.375,37.825 v2(67.96,37.825) ; v4@82.181,34.8 82.181,34.83 U15.N8@82.55,35.199 ; v4@99.812,41.933 U13.N8@100.202,42.323
  Bottom Layer w0.09: v2(67.96,37.825) 67.976,37.809 68.273,37.809 68.945,38.481 68.945,38.632 69.416,39.104 69.416,39.237 70.072,39.893 70.344,39.893 70.971,39.265 70.971,39.044 71.046,38.97 71.267,38.97 71.451,38.786 72.076,38.786 72.162,38.7 72.162,37.907 72.76,37.309 73.315,37.309 73.533,37.091 73.65,37.091 73.752,37.194 73.752,37.378 73.879,37.505 73.974,37.505 74.666,36.812 74.666,36.638 74.733,36.571 74.956,36.571 75.013,36.628 75.013,36.76 75.07,36.818 75.392,36.818 75.476,36.734 75.476,36.634 75.539,36.571 75.745,36.571 76,36.827 77.202,36.827 77.427,36.602 79.466,36.602 79.628,36.439 81.226,36.439 81.776,35.889 81.776,35.412 82.007,35.181 82.059,35.181 82.125,35.116 82.125,34.857 v4(82.178,34.804) 82.178,33.835 83.424,32.589 87.451,32.589 89.451,34.589 90.37,34.589 91.329,35.548 92.223,35.548 95.548,38.872 95.548,42.273 96.854,43.579 98.711,43.579 99.398,42.893 99.398,42.575 99.639,42.334 99.723,42.334 99.778,42.279 99.778,41.954 v4(99.803,41.929) 99.803,41.129 100.336,40.595 100.482,40.595 100.698,40.379 101.038,40.379 101.609,39.809 102.314,39.809 102.573,39.551 102.573,39.512 102.783,39.302 R189.1@102.878,39.302
DDR_BG0: R167.1 U1.H22 U13.M2 U15.M2 | length 61.5
  Top Layer w0.09: U1.H22@66.875,44.325 66.975,44.425 66.975,44.741 v2(66.967,44.749) ; U15.M2@83.374,39.997 83.374,40.045 v4@83.729,40.4 ; U13.M2@101.005,47.12 101.005,47.131 v4(101.403,47.529)
  Bottom Layer w0.09: v2(66.967,44.749) 66.982,44.764 67.401,44.764 67.807,45.17 81.305,45.17 81.407,45.067 81.407,44.374 81.676,44.105 81.676,43.837 81.757,43.756 81.909,43.756 81.989,43.837 81.989,44.221 81.701,44.509 81.701,44.64 81.816,44.754 81.931,44.754 82.366,44.319 82.366,43.542 82.29,43.465 81.865,43.465 81.587,43.187 81.587,42.498 81.701,42.384 81.701,41.879 81.908,41.672 81.908,41.371 82.275,41.004 83.55,41.004 83.778,40.776 v4(83.778,40.404) ; v4@83.781,40.4 83.995,40.186 83.995,39.946 84.178,39.763 84.178,39.269 84.735,38.711 85.94,38.711 86.948,39.719 87.542,39.719 88.314,40.492 88.314,41.558 88.996,42.239 88.996,42.793 96.063,49.86 98.692,49.86 99.365,49.187 99.365,48.614 99.856,48.122 100.844,48.122 101.359,47.607 101.359,47.536 101.658,47.237 101.658,47.045 101.798,46.905 101.798,46.549 102.493,45.854 103.365,45.854 103.465,45.954 103.606,45.954 103.961,46.309 105.151,46.309 106.888,48.045 106.888,48.284 107.015,48.411 107.015,48.634 107.933,49.552 107.938,49.552 108.128,49.742 108.268,49.742 R167.1@108.373,49.847
DDR_CASN: R187.1 U1.T22 U13.M8 U15.M8 | length 58
  Top Layer w0.09: U1.T22@66.875,40.325 66.875,39.764 v2@67.368,39.271 ; v4@82.981,34.83 U15.M8@83.35,35.199 ; v4(100.603,41.929) 100.994,42.32 U13.M8@101.005,42.32
  Bottom Layer w0.09: v2(67.372,39.271) 67.372,38.857 67.769,38.46 68.082,38.46 68.365,38.743 68.365,38.873 68.836,39.344 68.836,39.503 70.014,40.68 70.377,40.68 71.691,39.366 73.129,39.366 73.345,39.15 73.345,38.598 73.425,38.518 73.569,38.518 73.639,38.588 73.639,39.301 73.381,39.56 73.381,39.678 73.593,39.89 73.712,39.89 73.955,39.647 73.955,38.343 74.892,37.407 76.325,37.407 76.418,37.499 77.35,37.499 77.667,37.182 79.706,37.182 80.014,36.874 81.597,36.874 82.576,35.895 82.576,35.444 82.899,35.121 82.899,34.882 v4(82.978,34.804) 82.978,34.454 83.033,34.399 83.141,34.399 83.474,34.066 83.474,33.568 83.873,33.169 87.211,33.169 89.211,35.169 90.13,35.169 91.089,36.128 91.983,36.128 94.968,39.113 94.968,42.513 96.613,44.159 98.844,44.159 99.838,43.165 99.945,43.165 100.208,42.903 100.208,42.565 100.439,42.334 100.547,42.334 100.6,42.281 v4@100.6,41.931 ; v4(100.603,41.929) 100.603,41.863 101.203,41.263 101.203,40.855 101.763,40.294 102.684,40.294 102.974,40.004 104.01,40.004 104.473,39.541 104.473,39.512 104.683,39.302 R187.1@104.778,39.302
DDR_CKE: R171.1 U1.U21 U13.K2 U15.K2 | length 60.9
  Top Layer w0.09: U1.U21@66.375,39.825 66.402,39.852 66.402,39.998 66.605,40.201 66.605,40.483 v2(66.872,40.75) ; U15.K2@84.981,40 v4@85.381,40.4 ; U13.K2@102.612,47.132 v4@103.006,47.525
  Bottom Layer w0.09: v2(66.872,40.75) 66.872,41.23 66.523,41.578 66.523,41.909 66.731,42.117 66.731,43.258 66.48,43.509 66.48,43.629 66.343,43.766 66.343,44.997 67.694,46.348 81.983,46.348 84.803,43.529 84.803,42.178 85.381,41.6 v4@85.381,40.404 ; v4(85.378,40.404) v4@85.381,40.404 ; R171.1@104.678,49.952 104.791,49.952 104.853,49.891 104.853,49.313 105.198,48.968 105.198,48.315 104.411,47.529 v4(103.003,47.529) 103.003,47.976 103.168,48.142 103.168,48.783 102.728,49.223 102.728,49.556 100.744,51.54 96.103,51.54 87.752,43.189 87.752,42.131 87.375,41.754 87.375,41.193 87.061,40.879 86.239,40.879 85.764,40.404 v4@85.381,40.404
DDR_CLK_N: R181.2 U1.T24 U13.K8 U15.K8 | length 57.4
  Top Layer w0.09: U1.T24@67.875,40.325 67.875,40.479 67.946,40.55 67.946,40.817 v2(67.96,40.831) ; U15.K8@84.974,35.197 84.974,35.247 v4@85.327,35.6 ; U13.K8@102.605,42.32 103.003,42.718 v4(103.003,42.729)
  Bottom Layer w0.09: v2(67.96,40.831) 67.986,40.831 68.5,41.345 68.5,41.919 69.086,42.505 71.457,42.505 71.78,42.182 71.78,41.271 72.275,40.776 72.485,40.776 72.663,40.954 72.663,42.112 72.915,42.365 74.564,42.365 74.821,42.108 74.821,40.776 75.365,40.231 75.365,38.927 75.476,38.817 75.741,38.817 75.85,38.925 75.85,39.348 76.106,39.604 76.497,39.604 77.192,38.909 77.934,38.909 78.251,38.592 80.29,38.592 80.72,38.162 82.077,38.162 83.874,36.365 84.858,36.365 85.093,36.13 85.093,35.884 v4@85.373,35.604 ; v4(85.378,35.604) 85.091,35.317 85.091,35.206 85.218,35.079 85.54,35.079 86.714,36.253 87.699,36.253 88.046,36.6 89.567,36.6 90.504,37.538 91.399,37.538 93.558,39.697 93.558,43.097 96.029,45.569 99.392,45.569 101.463,43.498 102.415,43.498 102.709,43.204 102.709,42.999 102.979,42.729 v4(103.003,42.729) 102.728,42.454 102.728,42.313 102.866,42.175 104.869,42.175 105.198,42.504 R181.2@105.228,42.504
DDR_CLK_P: R181.1 U1.U23 U13.K7 U15.K7 | length 58.1
  Top Layer w0.09: U1.U23@67.375,39.825 U1.U23@67.375,39.825 67.376,40 67.46,40.084 v2(67.46,40.305) v2@67.424,40.269 ; v4@84.627,35.6 84.974,35.947 U15.K7@84.974,35.997 ; v4(102.203,42.729) 102.214,42.729 U13.K7@102.605,43.12
  Bottom Layer w0.09: v2(67.46,40.305) 67.508,40.305 67.688,40.486 68.103,40.486 68.305,40.688 68.305,40.796 68.75,41.241 68.75,41.816 69.189,42.255 71.354,42.255 71.53,42.079 71.53,41.168 72.171,40.526 72.589,40.526 72.913,40.85 72.913,42.009 73.019,42.115 74.46,42.115 74.571,42.004 74.571,40.672 75.115,40.128 75.115,38.824 75.372,38.567 75.845,38.567 76.1,38.822 76.1,39.244 76.21,39.354 76.394,39.354 77.089,38.659 77.83,38.659 78.148,38.342 80.187,38.342 80.617,37.912 81.974,37.912 83.77,36.115 84.755,36.115 84.843,36.026 84.843,35.87 v4(84.578,35.604) 84.841,35.341 84.841,35.103 85.115,34.829 85.643,34.829 86.817,36.003 87.803,36.003 88.149,36.35 89.67,36.35 90.608,37.288 91.502,37.288 93.808,39.593 93.808,42.994 96.133,45.319 99.289,45.319 101.36,43.248 102.311,43.248 102.459,43.1 102.459,42.985 v4(102.203,42.729) 102.478,42.454 102.478,42.209 102.762,41.925 104.859,41.925 105.18,41.604 R181.1@105.228,41.602
DDR_CSN: R183.1 U1.V24 U13.L7 U15.L7 | length 57
  Top Layer w0.09: U1.V24@67.875,39.325 67.879,39.329 v2(67.879,39.79) ; v4@83.781,35.6 83.812,35.6 84.15,35.938 U15.L7@84.15,35.999 ; v4(101.403,42.729) 101.414,42.729 U13.L7@101.805,43.12
  Bottom Layer w0.09: v2(67.879,39.79) 67.879,39.822 68.595,40.539 68.595,40.676 69.471,41.552 70.735,41.552 72.051,40.236 72.709,40.236 73.203,40.73 73.203,41.722 73.306,41.825 74.159,41.825 74.278,41.705 74.278,40.555 74.825,40.008 74.825,38.704 75.252,38.277 75.965,38.277 76.428,38.739 76.598,38.739 76.968,38.369 77.71,38.369 78.028,38.052 80.066,38.052 80.482,37.636 81.896,37.636 83.579,35.953 83.579,35.881 83.778,35.682 v4(83.778,35.604) 83.778,35.554 84.128,35.204 84.231,35.204 84.896,34.539 86.126,34.539 86.28,34.694 86.28,35.044 86.42,35.184 87.941,35.184 88.816,36.059 89.79,36.059 90.728,36.998 91.622,36.998 94.098,39.473 94.098,42.874 96.253,45.029 99.205,45.029 101.181,43.053 101.181,42.978 101.403,42.756 v4(101.403,42.729) 102.514,41.618 102.877,41.618 103.109,41.386 103.827,41.386 ; 103.828,41.385 104.33,41.385 104.573,41.143 104.573,40.825 104.814,40.584 105.898,40.584 106.328,40.154 106.826,40.154 R183.1@106.853,40.127
DDR_DQ0: U1.AB26 U15.F7 | length 22.9
  Top Layer w0.09: U1.AB26@68.875,37.325 68.893,37.343 69.03,37.343 69.276,37.59 69.483,37.59 69.557,37.515 69.962,37.515 72.793,34.684 75.309,34.684 76.047,35.423 76.469,35.423 76.781,35.111 77.439,35.111 77.64,34.91 78.46,34.91 79.381,35.83 79.381,36.288 79.753,36.661 86.059,36.661 86.305,36.415 86.426,36.415 86.673,36.661 86.773,36.661 87.05,36.384 87.28,36.384 87.472,36.576 87.655,36.576 87.754,36.477 87.754,36.185 87.939,36 U15.F7@88.175,36
DDR_DQ1: U1.AC26 U15.H7 | length 24.1
  Top Layer w0.09: U1.AC26@68.875,36.825 69.056,37.006 69.203,37.006 69.271,37.075 69.479,37.075 69.547,37.006 69.651,37.006 72.553,34.104 78.431,34.104 78.667,33.868 78.774,33.868 79.264,34.358 79.642,34.358 80.002,33.997 80.002,33.744 79.44,33.181 79.44,32.851 79.674,32.616 82.553,32.616 82.729,32.792 83.245,32.792 ; 83.246,32.792 83.384,32.655 85.088,32.655 86.131,33.698 86.131,34.192 86.176,34.236 86.176,35.595 ; 86.176,35.595 U15.H7@86.581,36
DDR_DQ2: U1.AB27 U15.J7 | length 21.9
  Top Layer w0.09: U1.AB27@69.382,37.318 U1.AB27@69.375,37.325 69.742,37.325 72.673,34.394 75.903,34.394 76.009,34.501 76.009,34.974 76.167,35.133 76.349,35.133 76.546,34.935 76.546,34.497 76.638,34.406 77.583,34.406 77.797,34.62 78.376,34.62 78.643,34.353 78.836,34.353 79.366,34.883 79.366,35.15 79.445,35.229 79.714,35.229 80.005,35.521 80.005,35.664 79.875,35.795 79.774,35.795 79.671,35.898 79.671,36.168 79.873,36.371 80.326,36.371 80.504,36.193 80.625,36.193 80.804,36.371 81.142,36.371 81.316,36.197 81.408,36.197 81.583,36.371 81.913,36.371 82.086,36.198 82.191,36.198 82.363,36.371 82.688,36.371 82.867,36.192 83.077,36.192 83.256,36.371 83.564,36.371 83.733,36.202 83.891,36.202 84.06,36.371 84.354,36.371 84.521,36.205 84.693,36.205 84.86,36.371 85.4,36.371 U15.J7@85.774,35.997
DDR_DQ3: U1.AC27 U15.H8 | length 23.7
  Top Layer w0.09: U1.AC27@69.35,36.825 U1.AC27@69.375,36.825 69.422,36.825 72.433,33.814 78.307,33.814 78.543,33.578 78.894,33.578 79.384,34.068 79.521,34.068 79.665,33.924 79.665,33.817 79.15,33.301 79.15,32.731 79.554,32.326 82.674,32.326 82.849,32.502 83.095,32.502 83.233,32.365 85.208,32.365 86.289,33.445 86.824,33.445 86.932,33.553 86.932,34.839 U15.H8@86.574,35.197
DDR_DQ4: U1.W25 U15.J3 | length 24.8
  Top Layer w0.09: U1.W25@68.375,38.825 68.625,39.075 69.479,39.075 69.503,39.05 71.246,39.05 73.622,36.674 74.485,36.674 75.948,38.137 76.504,38.137 77.893,39.527 78.085,39.527 78.231,39.381 78.741,39.381 78.891,39.231 79.151,39.231 79.229,39.153 79.229,39.006 79.164,38.941 78.725,38.941 78.576,39.09 77.892,39.09 77.783,38.981 77.783,38.887 77.896,38.773 78.424,38.773 78.613,38.585 78.857,38.585 78.923,38.651 79.303,38.651 79.431,38.779 80.319,38.779 80.443,38.904 80.569,38.904 80.82,38.653 80.918,38.653 81.214,38.949 81.317,38.949 81.592,38.674 81.737,38.674 81.984,38.921 82.159,38.921 82.397,38.683 82.548,38.683 82.813,38.949 82.932,38.949 83.23,38.651 83.338,38.651 83.665,38.978 83.792,38.978 84.119,38.651 84.234,38.651 84.487,38.904 84.616,38.904 84.862,38.658 85.235,38.658 U15.J3@85.774,39.197
DDR_DQ5: U1.W27 U15.H2 | length 23.8
  Top Layer w0.09: U1.W27@69.375,38.846 U1.W27@69.375,38.825 ; U1.W27@69.389,38.811 U1.W27@69.375,38.825 ; U15.H2@86.572,39.999 86.265,39.999 86.195,39.929 86.195,38.811 86.054,38.67 85.657,38.67 85.348,38.361 79.043,38.361 77.738,37.056 77.593,37.056 77.52,37.128 77.52,37.256 78.448,38.184 78.448,38.338 78.302,38.483 77.776,38.483 77.578,38.682 77.459,38.682 76.624,37.847 76.068,37.847 74.605,36.384 73.5,36.384 71.06,38.825 U1.W27@69.375,38.825
DDR_DQ6: U1.W26 U15.H3 | length 24.4
  Top Layer w0.09: U1.W26@68.875,38.825 68.899,38.825 69.163,38.561 69.529,38.561 69.573,38.605 70.87,38.605 73.38,36.094 74.725,36.094 76.188,37.557 76.341,37.557 76.397,37.501 76.839,37.501 76.95,37.611 76.95,37.763 77.034,37.848 77.285,37.848 77.381,37.943 77.381,38.191 77.48,38.29 77.559,38.29 77.656,38.193 77.75,38.193 77.828,38.116 77.828,37.974 77.23,37.376 77.23,37.008 77.472,36.766 77.858,36.766 79.163,38.071 86.867,38.071 86.92,38.124 86.92,38.285 86.818,38.388 86.664,38.388 86.573,38.478 U15.H3@86.573,39.196
DDR_DQ7: U1.Y25 U15.G2 | length 25.1
  Top Layer w0.09: U1.Y25@68.381,38.319 68.594,38.319 68.646,38.37 69.652,38.37 69.692,38.41 70.652,38.41 73.258,35.804 74.845,35.804 76.252,37.211 76.855,37.211 76.94,37.125 76.94,36.888 77.226,36.602 77.226,36.397 77.288,36.334 77.45,36.334 77.547,36.431 77.708,36.431 78.015,36.123 78.09,36.123 78.261,36.294 78.261,36.752 79.289,37.781 87.016,37.781 87.226,37.991 87.226,38.504 86.876,38.853 86.876,38.962 86.999,39.084 86.999,39.304 86.783,39.52 86.783,39.661 86.888,39.766 87.143,39.766 U15.G2@87.374,39.997
DDR_DQ8: U1.R27 U15.D7 | length 38.6
  Top Layer w0.09: U1.R27@69.375,40.825 69.378,40.828 69.625,40.828 69.669,40.872 75.114,40.872 78.946,44.704 89.629,44.704 90.014,44.704 93.806,40.913 93.806,38.866 93.689,38.749 93.499,38.749 93.26,38.51 93.26,38.412 93.806,37.866 93.806,36.709 93.666,36.569 93.511,36.569 93.243,36.837 92.739,36.837 92.552,36.65 92.552,36.218 92.739,36.032 92.739,35.792 92.598,35.652 91.053,35.652 90.954,35.751 90.954,36.248 90.861,36.342 90.119,36.342 U15.D7@89.774,35.997
DDR_DQ9: U1.R26 U15.B8 | length 39.3
  Top Layer w0.09: U1.R26@68.875,40.825 69.125,41.075 69.479,41.075 69.489,41.085 74.917,41.085 78.826,44.994 90.135,44.994 94.096,41.033 94.096,36.589 93.995,36.489 93.995,36.003 93.913,35.921 93.631,35.921 93.474,36.078 93.474,36.196 93.123,36.547 92.919,36.547 92.842,36.47 92.842,36.339 93.144,36.037 93.144,35.787 93.537,35.393 93.537,35.127 93.261,34.85 91.942,34.85 91.631,35.161 91.41,35.161 U15.B8@91.374,35.197
DDR_DQ10: U1.P27 U15.C7 | length 39.6
  Top Layer w0.09: U1.P27@69.375,41.325 74.747,41.325 78.706,45.284 90.255,45.284 94.386,41.153 94.386,35.551 92.886,34.052 92.031,34.052 91.782,34.301 91.782,34.503 91.487,34.797 91.286,34.797 91.001,35.082 91.001,35.294 90.58,35.715 90.58,35.991 U15.C7@90.574,35.997
DDR_DQ11: U1.P26 U15.C8 | length 41.4
  Top Layer w0.09: U1.P26@68.875,41.325 69.072,41.325 69.125,41.378 69.125,41.429 69.282,41.585 69.528,41.585 69.584,41.528 74.54,41.528 78.584,45.572 ; 78.584,45.574 90.375,45.574 94.676,41.273 94.676,35.431 93.006,33.762 92.015,33.762 91.732,33.479 91.393,33.479 91.027,33.845 91.027,34.459 90.574,34.911 U15.C8@90.574,35.197
DDR_DQ12: U1.V26 U15.C3 | length 39.6
  Top Layer w0.09: U1.V26@68.875,39.325 69.007,39.325 69.267,39.585 71.533,39.585 73.864,37.254 74.245,37.254 75.707,38.717 76.263,38.717 79.358,41.811 79.358,41.943 79.247,42.054 79.141,42.054 76.101,39.013 76.009,39.013 75.886,39.137 75.886,39.237 79.651,43.002 87.724,43.002 88.1,42.627 88.216,42.627 88.591,43.002 89.002,43.002 89.291,42.713 89.291,42.446 89.091,42.247 89.091,42.131 89.17,42.051 89.971,42.051 90.048,41.974 90.048,41.841 89.966,41.758 89.48,41.758 89.382,41.66 89.382,40.65 89.63,40.403 90.018,40.403 90.174,40.247 90.174,39.86 90.574,39.46 U15.C3@90.574,39.197
DDR_DQ13: U1.V27 U15.D3 | length 39.8
  Top Layer w0.09: U1.V27@69.385,39.335 U1.V27@69.375,39.325 71.383,39.325 73.744,36.964 74.365,36.964 75.828,38.427 76.384,38.427 79.197,41.24 79.329,41.24 79.432,41.137 79.432,41.033 78.274,39.875 78.274,39.748 78.347,39.675 78.498,39.675 78.77,39.946 78.889,39.946 78.95,39.885 78.95,39.581 79.011,39.521 79.174,39.521 79.252,39.599 79.252,40.308 79.334,40.391 79.478,40.391 79.696,40.173 79.859,40.173 80.003,40.316 80.003,40.458 79.932,40.528 79.777,40.528 79.667,40.638 79.667,40.845 79.806,40.983 79.806,41.187 79.682,41.311 79.682,42.08 79.489,42.273 79.489,42.408 79.794,42.712 87.589,42.712 88.072,42.228 88.228,42.228 88.711,42.712 88.882,42.712 88.935,42.659 88.935,42.517 88.722,42.304 88.722,42.076 88.874,41.924 88.874,41.789 88.801,41.717 88.659,41.717 88.459,41.917 87.97,41.917 87.793,42.094 87.689,42.094 87.642,42.048 cw(c87.354,42.317) 87.623,42.028 87.512,41.917 87.209,41.917 87.13,41.838 87.13,41.77 87.274,41.626 87.425,41.626 87.5,41.55 ; 87.5,41.553 87.5,41.55 ; U15.D3@89.772,39.197 89.405,39.563 89.405,40.137 89.145,40.397 88.021,40.397 87.766,40.653 87.766,40.908 88.024,41.166 88.449,41.166 88.555,41.273 88.555,41.401 88.344,41.612 87.931,41.612 87.827,41.507 87.827,41.381 87.719,41.274 87.575,41.274 87.5,41.348 87.5,41.55
DDR_DQ14: U1.V25 U15.C2 | length 39.8
  Top Layer w0.09: U1.V25@68.375,39.325 68.5,39.45 68.646,39.45 68.771,39.575 68.979,39.575 69.179,39.775 71.753,39.775 73.984,37.544 74.12,37.544 74.212,37.637 74.212,37.732 72.593,39.352 72.593,39.444 72.693,39.543 72.812,39.543 74.407,37.948 74.524,37.948 74.631,38.055 74.631,38.152 73.446,39.337 73.446,39.462 73.527,39.543 73.642,39.543 74.809,38.377 74.918,38.377 75.012,38.471 75.012,38.595 74.258,39.349 74.258,39.463 74.339,39.543 74.479,39.543 75.211,38.812 75.347,38.812 75.429,38.894 75.429,39.037 75.119,39.347 75.119,39.468 75.195,39.543 75.408,39.543 75.544,39.407 75.643,39.407 79.528,43.292 89.122,43.292 89.832,42.582 90.084,42.582 90.464,42.202 90.464,41.809 90.179,41.523 90.179,40.704 90.574,40.309 U15.C2@90.574,39.997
